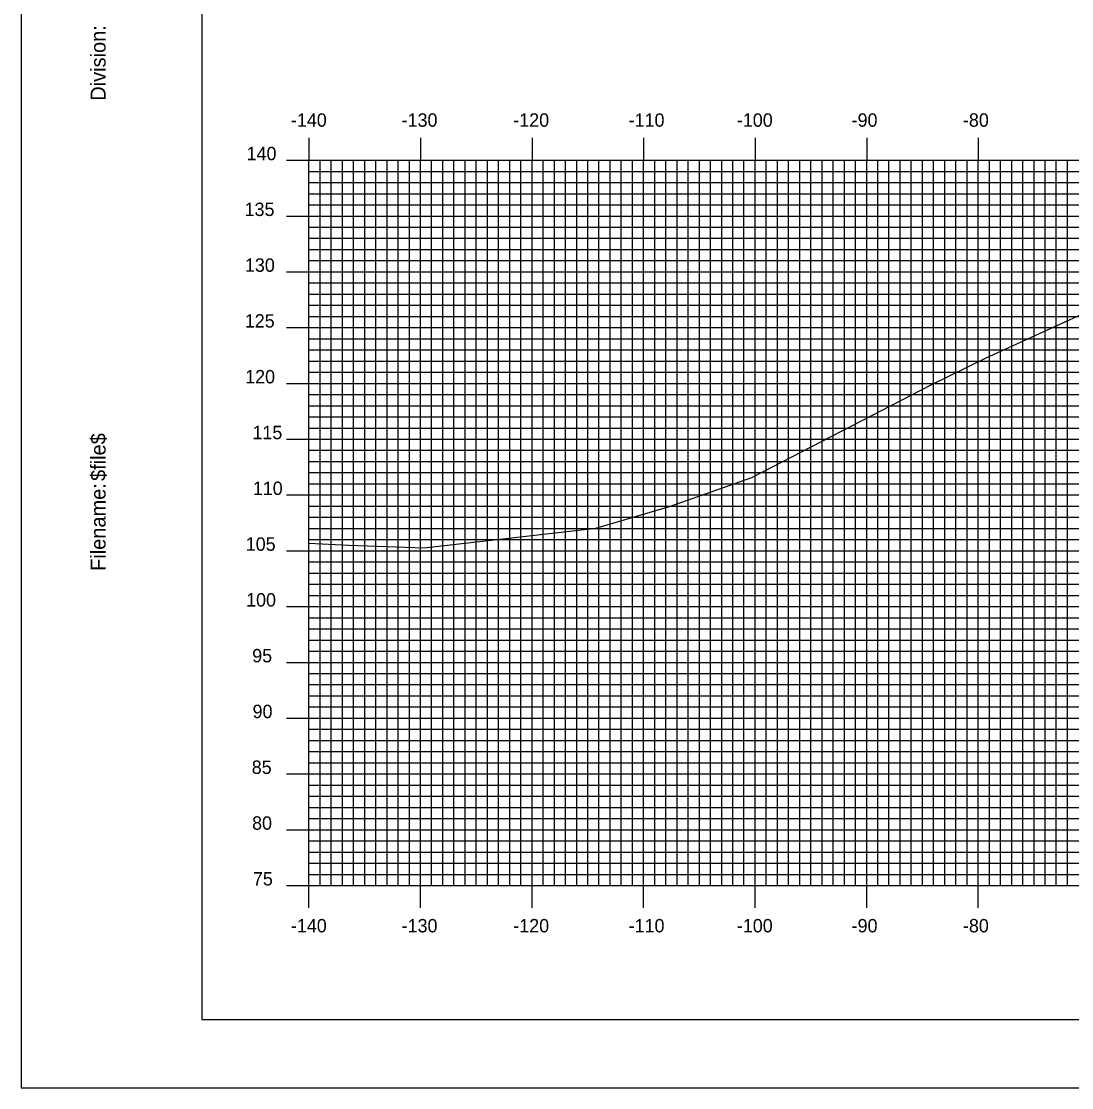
# Model space of a CAD drawing. Extents: x 859471 to 859814, y 364765 to 364985.
# Drawn here: x 859471.1 to 859565.3, y 364765.2 to 364860.7 of the extents above; entities that cross this region are included whole.
import ezdxf

# ---------------------------------------------------------------- set-up
doc = ezdxf.new("R2010")
doc.units = 0
for name, color, linetype in [('BORDER', 7, 'Continuous'), ('H_V ANNOTATION', 7, 'Continuous'), ('MAJOR', 7, 'Continuous'), ('MINOR', 7, 'Continuous'), ('PLOT BOUNDARY', 7, 'Continuous'), ('S_Roadway_Centerline', 7, 'Continuous')]:
    doc.layers.add(name, color=color, linetype=linetype)

msp = doc.modelspace()

# ---------------------------------------------------------------- linework, layer by layer
at = {"layer": 'BORDER'}
msp.add_lwpolyline([(859487.273, 364771.302), (859807.273, 364771.302), (859807.273, 364981.302), (859487.273, 364981.302)], close=True, dxfattribs=at)
at = {"layer": 'MAJOR'}
for p, q in [((859496.873, 364850.306), (859496.873, 364848.302)), ((859506.873, 364850.306), (859506.873, 364848.302)), ((859516.873, 364850.306), (859516.873, 364848.302)), ((859526.873, 364850.306), (859526.873, 364848.302)), ((859536.873, 364850.306), (859536.873, 364848.302)), ((859546.873, 364850.306), (859546.873, 364848.302)), ((859556.873, 364850.306), (859556.873, 364848.302)), ((859494.869, 364848.302), (859496.873, 364848.302)), ((859496.873, 364848.302), (859776.873, 364848.302)), ((859496.873, 364783.302), (859496.873, 364848.302)), ((859496.873, 364783.302), (859496.873, 364848.302)), ((859496.873, 364848.302), (859776.873, 364848.302)), ((859506.873, 364783.302), (859506.873, 364848.302)), ((859516.873, 364783.302), (859516.873, 364848.302)), ((859526.873, 364783.302), (859526.873, 364848.302)), ((859536.873, 364783.302), (859536.873, 364848.302)), ((859546.873, 364783.302), (859546.873, 364848.302)), ((859556.873, 364783.302), (859556.873, 364848.302)), ((859494.869, 364843.302), (859496.873, 364843.302)), ((859496.873, 364843.302), (859776.873, 364843.302)), ((859494.869, 364838.302), (859496.873, 364838.302)), ((859496.873, 364838.302), (859776.873, 364838.302)), ((859494.869, 364833.302), (859496.873, 364833.302)), ((859496.873, 364833.302), (859776.873, 364833.302)), ((859494.869, 364828.302), (859496.873, 364828.302)), ((859496.873, 364828.302), (859776.873, 364828.302)), ((859494.869, 364823.302), (859496.873, 364823.302)), ((859496.873, 364823.302), (859776.873, 364823.302)), ((859494.869, 364818.302), (859496.873, 364818.302)), ((859496.873, 364818.302), (859776.873, 364818.302)), ((859494.869, 364813.302), (859496.873, 364813.302)), ((859496.873, 364813.302), (859776.873, 364813.302)), ((859494.869, 364808.302), (859496.873, 364808.302)), ((859496.873, 364808.302), (859776.873, 364808.302)), ((859494.869, 364803.302), (859496.873, 364803.302)), ((859496.873, 364803.302), (859776.873, 364803.302)), ((859494.869, 364798.302), (859496.873, 364798.302)), ((859496.873, 364798.302), (859776.873, 364798.302)), ((859494.869, 364793.302), (859496.873, 364793.302)), ((859496.873, 364793.302), (859776.873, 364793.302)), ((859494.869, 364788.302), (859496.873, 364788.302)), ((859496.873, 364788.302), (859776.873, 364788.302)), ((859494.869, 364783.302), (859496.873, 364783.302)), ((859496.873, 364783.302), (859776.873, 364783.302)), ((859496.873, 364783.302), (859776.873, 364783.302)), ((859496.873, 364781.298), (859496.873, 364783.302)), ((859506.873, 364781.298), (859506.873, 364783.302)), ((859516.873, 364781.298), (859516.873, 364783.302)), ((859526.873, 364781.298), (859526.873, 364783.302)), ((859536.873, 364781.298), (859536.873, 364783.302)), ((859546.873, 364781.298), (859546.873, 364783.302)), ((859556.873, 364781.298), (859556.873, 364783.302))]:
    msp.add_line(p, q, dxfattribs=at)
at = {"layer": 'MINOR'}
for p, q in [((859497.873, 364783.302), (859497.873, 364848.302)), ((859498.873, 364783.302), (859498.873, 364848.302)), ((859499.873, 364783.302), (859499.873, 364848.302)), ((859500.873, 364783.302), (859500.873, 364848.302)), ((859501.873, 364783.302), (859501.873, 364848.302)), ((859502.873, 364783.302), (859502.873, 364848.302)), ((859503.873, 364783.302), (859503.873, 364848.302)), ((859504.873, 364783.302), (859504.873, 364848.302)), ((859505.873, 364783.302), (859505.873, 364848.302)), ((859507.873, 364783.302), (859507.873, 364848.302)), ((859508.873, 364783.302), (859508.873, 364848.302)), ((859509.873, 364783.302), (859509.873, 364848.302)), ((859510.873, 364783.302), (859510.873, 364848.302)), ((859511.873, 364783.302), (859511.873, 364848.302)), ((859512.873, 364783.302), (859512.873, 364848.302)), ((859513.873, 364783.302), (859513.873, 364848.302)), ((859514.873, 364783.302), (859514.873, 364848.302)), ((859515.873, 364783.302), (859515.873, 364848.302)), ((859517.873, 364783.302), (859517.873, 364848.302)), ((859518.873, 364783.302), (859518.873, 364848.302)), ((859519.873, 364783.302), (859519.873, 364848.302)), ((859520.873, 364783.302), (859520.873, 364848.302)), ((859521.873, 364783.302), (859521.873, 364848.302)), ((859522.873, 364783.302), (859522.873, 364848.302)), ((859523.873, 364783.302), (859523.873, 364848.302)), ((859524.873, 364783.302), (859524.873, 364848.302)), ((859525.873, 364783.302), (859525.873, 364848.302)), ((859527.873, 364783.302), (859527.873, 364848.302)), ((859528.873, 364783.302), (859528.873, 364848.302)), ((859529.873, 364783.302), (859529.873, 364848.302)), ((859530.873, 364783.302), (859530.873, 364848.302)), ((859531.873, 364783.302), (859531.873, 364848.302)), ((859532.873, 364783.302), (859532.873, 364848.302)), ((859533.873, 364783.302), (859533.873, 364848.302)), ((859534.873, 364783.302), (859534.873, 364848.302)), ((859535.873, 364783.302), (859535.873, 364848.302)), ((859537.873, 364783.302), (859537.873, 364848.302)), ((859538.873, 364783.302), (859538.873, 364848.302)), ((859539.873, 364783.302), (859539.873, 364848.302)), ((859540.873, 364783.302), (859540.873, 364848.302)), ((859541.873, 364783.302), (859541.873, 364848.302)), ((859542.873, 364783.302), (859542.873, 364848.302)), ((859543.873, 364783.302), (859543.873, 364848.302)), ((859544.873, 364783.302), (859544.873, 364848.302)), ((859545.873, 364783.302), (859545.873, 364848.302)), ((859547.873, 364783.302), (859547.873, 364848.302)), ((859548.873, 364783.302), (859548.873, 364848.302)), ((859549.873, 364783.302), (859549.873, 364848.302)), ((859550.873, 364783.302), (859550.873, 364848.302)), ((859551.873, 364783.302), (859551.873, 364848.302)), ((859552.873, 364783.302), (859552.873, 364848.302)), ((859553.873, 364783.302), (859553.873, 364848.302)), ((859554.873, 364783.302), (859554.873, 364848.302)), ((859555.873, 364783.302), (859555.873, 364848.302)), ((859557.873, 364783.302), (859557.873, 364848.302)), ((859558.873, 364783.302), (859558.873, 364848.302)), ((859559.873, 364783.302), (859559.873, 364848.302)), ((859560.873, 364783.302), (859560.873, 364848.302)), ((859561.873, 364783.302), (859561.873, 364848.302)), ((859562.873, 364783.302), (859562.873, 364848.302)), ((859563.873, 364783.302), (859563.873, 364848.302)), ((859564.873, 364783.302), (859564.873, 364848.302)), ((859496.873, 364847.302), (859776.873, 364847.302)), ((859496.873, 364847.302), (859498.877, 364847.302)), ((859496.873, 364846.302), (859776.873, 364846.302)), ((859496.873, 364846.302), (859498.877, 364846.302)), ((859496.873, 364845.302), (859776.873, 364845.302)), ((859496.873, 364845.302), (859498.877, 364845.302)), ((859496.873, 364844.302), (859776.873, 364844.302)), ((859496.873, 364844.302), (859498.877, 364844.302)), ((859496.873, 364842.302), (859776.873, 364842.302)), ((859496.873, 364842.302), (859498.877, 364842.302)), ((859496.873, 364841.302), (859776.873, 364841.302)), ((859496.873, 364841.302), (859498.877, 364841.302)), ((859496.873, 364840.302), (859776.873, 364840.302)), ((859496.873, 364840.302), (859498.877, 364840.302)), ((859496.873, 364839.302), (859776.873, 364839.302)), ((859496.873, 364839.302), (859498.877, 364839.302)), ((859496.873, 364837.302), (859776.873, 364837.302)), ((859496.873, 364837.302), (859498.877, 364837.302)), ((859496.873, 364836.302), (859776.873, 364836.302)), ((859496.873, 364836.302), (859498.877, 364836.302)), ((859496.873, 364835.302), (859776.873, 364835.302)), ((859496.873, 364835.302), (859498.877, 364835.302)), ((859496.873, 364834.302), (859776.873, 364834.302)), ((859496.873, 364834.302), (859498.877, 364834.302)), ((859496.873, 364832.302), (859776.873, 364832.302)), ((859496.873, 364832.302), (859498.877, 364832.302)), ((859496.873, 364831.302), (859776.873, 364831.302)), ((859496.873, 364831.302), (859498.877, 364831.302)), ((859496.873, 364830.302), (859776.873, 364830.302)), ((859496.873, 364830.302), (859498.877, 364830.302)), ((859496.873, 364829.302), (859776.873, 364829.302)), ((859496.873, 364829.302), (859498.877, 364829.302)), ((859496.873, 364827.302), (859776.873, 364827.302)), ((859496.873, 364827.302), (859498.877, 364827.302)), ((859496.873, 364826.302), (859776.873, 364826.302)), ((859496.873, 364826.302), (859498.877, 364826.302)), ((859496.873, 364825.302), (859776.873, 364825.302)), ((859496.873, 364825.302), (859498.877, 364825.302)), ((859496.873, 364824.302), (859776.873, 364824.302)), ((859496.873, 364824.302), (859498.877, 364824.302)), ((859496.873, 364822.302), (859776.873, 364822.302)), ((859496.873, 364822.302), (859498.877, 364822.302)), ((859496.873, 364821.302), (859776.873, 364821.302)), ((859496.873, 364821.302), (859498.877, 364821.302)), ((859496.873, 364820.302), (859776.873, 364820.302)), ((859496.873, 364820.302), (859498.877, 364820.302)), ((859496.873, 364819.302), (859776.873, 364819.302)), ((859496.873, 364819.302), (859498.877, 364819.302)), ((859496.873, 364817.302), (859776.873, 364817.302)), ((859496.873, 364817.302), (859498.877, 364817.302)), ((859496.873, 364816.302), (859776.873, 364816.302)), ((859496.873, 364816.302), (859498.877, 364816.302)), ((859496.873, 364815.302), (859776.873, 364815.302)), ((859496.873, 364815.302), (859498.877, 364815.302)), ((859496.873, 364814.302), (859776.873, 364814.302)), ((859496.873, 364814.302), (859498.877, 364814.302)), ((859496.873, 364812.302), (859776.873, 364812.302)), ((859496.873, 364812.302), (859498.877, 364812.302)), ((859496.873, 364811.302), (859776.873, 364811.302)), ((859496.873, 364811.302), (859498.877, 364811.302)), ((859496.873, 364810.302), (859776.873, 364810.302)), ((859496.873, 364810.302), (859498.877, 364810.302)), ((859496.873, 364809.302), (859776.873, 364809.302)), ((859496.873, 364809.302), (859498.877, 364809.302)), ((859496.873, 364807.302), (859776.873, 364807.302)), ((859496.873, 364807.302), (859498.877, 364807.302)), ((859496.873, 364806.302), (859776.873, 364806.302)), ((859496.873, 364806.302), (859498.877, 364806.302)), ((859496.873, 364805.302), (859776.873, 364805.302)), ((859496.873, 364805.302), (859498.877, 364805.302)), ((859496.873, 364804.302), (859776.873, 364804.302)), ((859496.873, 364804.302), (859498.877, 364804.302)), ((859496.873, 364802.302), (859776.873, 364802.302)), ((859496.873, 364802.302), (859498.877, 364802.302)), ((859496.873, 364801.302), (859776.873, 364801.302)), ((859496.873, 364801.302), (859498.877, 364801.302)), ((859496.873, 364800.302), (859776.873, 364800.302)), ((859496.873, 364800.302), (859498.877, 364800.302)), ((859496.873, 364799.302), (859776.873, 364799.302)), ((859496.873, 364799.302), (859498.877, 364799.302)), ((859496.873, 364797.302), (859776.873, 364797.302)), ((859496.873, 364797.302), (859498.877, 364797.302)), ((859496.873, 364796.302), (859776.873, 364796.302)), ((859496.873, 364796.302), (859498.877, 364796.302)), ((859496.873, 364795.302), (859776.873, 364795.302)), ((859496.873, 364795.302), (859498.877, 364795.302)), ((859496.873, 364794.302), (859776.873, 364794.302)), ((859496.873, 364794.302), (859498.877, 364794.302)), ((859496.873, 364792.302), (859776.873, 364792.302)), ((859496.873, 364792.302), (859498.877, 364792.302)), ((859496.873, 364791.302), (859776.873, 364791.302)), ((859496.873, 364791.302), (859498.877, 364791.302)), ((859496.873, 364790.302), (859776.873, 364790.302)), ((859496.873, 364790.302), (859498.877, 364790.302)), ((859496.873, 364789.302), (859776.873, 364789.302)), ((859496.873, 364789.302), (859498.877, 364789.302)), ((859496.873, 364787.302), (859776.873, 364787.302)), ((859496.873, 364787.302), (859498.877, 364787.302)), ((859496.873, 364786.302), (859776.873, 364786.302)), ((859496.873, 364786.302), (859498.877, 364786.302)), ((859496.873, 364785.302), (859776.873, 364785.302)), ((859496.873, 364785.302), (859498.877, 364785.302)), ((859496.873, 364784.302), (859776.873, 364784.302)), ((859496.873, 364784.302), (859498.877, 364784.302))]:
    msp.add_line(p, q, dxfattribs=at)
at = {"layer": 'PLOT BOUNDARY'}
msp.add_lwpolyline([(859471.086, 364765.184), (859811.086, 364765.184), (859811.086, 364985.184), (859471.086, 364985.184)], close=True, dxfattribs=at)
at = {"layer": 'S_Roadway_Centerline'}
msp.add_lwpolyline([(859496.873, 364813.975), (859500.423, 364813.806), (859507.188, 364813.561), (859522.602, 364815.323), (859529.195, 364817.264), (859536.581, 364819.874), (859552.667, 364828.184), (859557.574, 364830.597), (859566.091, 364834.481), (859574.422, 364837.987), (859585.19, 364838.631), (859593.654, 364839.158), (859615.671, 364839.903), (859625.157, 364840.217), (859630.585, 364840.301), (859644.73, 364840.544), (859658.145, 364834.91), (859667.119, 364831.057)], dxfattribs=at)

# ---------------------------------------------------------------- texts
at = {"layer": 'BORDER'}
for s, p in [('Division:', (859478.643, 364853.634)), ('$file$', (859478.643, 364819.553)), ('Filename:', (859478.643, 364811.499))]:
    msp.add_text(s, height=1.3392, rotation=90, dxfattribs=at).set_placement(p)
at = {"layer": 'H_V ANNOTATION'}
for s, p in [('-140', (859495.257, 364851.302)), ('-130', (859505.182, 364851.302)), ('-120', (859515.193, 364851.302)), ('-110', (859525.535, 364851.302)), ('-100', (859535.236, 364851.302)), ('-90', (859545.524, 364851.302)), ('-80', (859555.503, 364851.302)), ('140', (859491.283, 364848.302)), ('135', (859491.101, 364843.302)), ('130', (859491.133, 364838.302)), ('125', (859491.122, 364833.302)), ('120', (859491.154, 364828.302)), ('115', (859491.808, 364823.302)), ('110', (859491.84, 364818.302)), ('105', (859491.208, 364813.302)), ('100', (859491.24, 364808.302)), ('95', (859491.786, 364803.302)), ('90', (859491.818, 364798.302)), ('85', (859491.743, 364793.302)), ('80', (859491.775, 364788.302)), ('75', (859491.849, 364783.302)), ('-140', (859495.257, 364779.102)), ('-130', (859505.182, 364779.102)), ('-120', (859515.193, 364779.102)), ('-110', (859525.535, 364779.102)), ('-100', (859535.236, 364779.102)), ('-90', (859545.524, 364779.102)), ('-80', (859555.503, 364779.102))]:
    msp.add_text(s, height=1.2, dxfattribs=at).set_placement(p)
at = {"layer": 'MAJOR'}
msp.add_text('-', height=0.012, dxfattribs=at).set_placement((859496.864, 364783.302))

doc.saveas('drawing.dxf')
